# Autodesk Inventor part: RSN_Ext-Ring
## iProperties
Author: John Muchow
Shininess: 70.0
PropertySet Name: _Private Model Information
Created: 2001-05
Part Number: RSN_Ext-Ring
Document SubType Name: Modeling
Designer: John Muchow
Material: UNS S31600
Description: Spirolox 0.704 in ID x 0.042 in Thick
Control State: 0
Master: False
Checked Out: False
PropertySet Name: Design Tracking Control
Density: 8.03
Volumn: 0.16740708221168904
Area: 8.181947143325539
PropertySet Name: Model Information
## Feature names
1. Loft1
2. Revolution1
3. Revolution2
4. Extrusion1
5. Extrusion2
